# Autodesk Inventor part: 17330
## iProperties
Company: TraceParts S.A.
Created: 2011-04
Part Number: 17330
Checked By: TraceParts S.A.
Catalog Web Link: www.traceparts.com
Document SubType Name: Modeling
Designer: TraceParts
Author: TraceParts
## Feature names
1. 耆㦊縬
2. 耆㦊縬
